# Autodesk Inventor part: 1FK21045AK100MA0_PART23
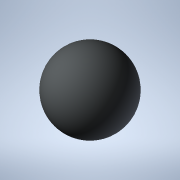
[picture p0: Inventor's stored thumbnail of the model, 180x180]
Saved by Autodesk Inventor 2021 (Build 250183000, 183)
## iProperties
Created: 2025-04
Part Number: 1FK21045AK100MA0_PART23
Material: Generic
Catalog Web Link: www.3dfindit.com
Description: -Servo synchronous motor
Document SubType Name: Modeling
Designer: psAdmin
Mass: 0.137258 g
Surface Area: 1.2868 cm^2
Volume: 0.137258 cm^3
Density: 1 g/cm^3
Appearance: PSOLRGB-212-217-219
Category: PARTsolutions
Title: 1FK21045AK100MA0_PART23
Author: Cadenas PARTsolutions
Comments: Servo synchronous motor
Sending System: PARTsolutions
Preprocessor: ST-DEVELOPER v19.3
PSOL_IDENT_0: {$CADENAS_DATA/23d-libs/siemens_ag/_cat_/e0/5f/1fk21045ak100ma0.prj},216 {VTYP=3D},{NB=1FK21045AK100
PSOL_IDENT_1: MA0_PART23},{LINA=1FK21045AK100MA0_PART23},{NN=1FK21045AK100MA0_PART23},{NOPRJ=TRUE},{DATE=19.08.202
PSOL_IDENT_2: 5 14:01:03},{GEOMDATE=30.07.2025 02:01:57},{VERSION=},{LINEID=10},{WBVAR=},{WBNUMERIC=}  {NB=1FK2104
PSOL_IDENT_3: 5AK100MA0_PART23},{LINA=1FK21045AK100MA0_PART23},{KT=DUMMY},{PREVIEW=../../../_pool_/0f/2c/p_d211_xx
PSOL_IDENT_4: _00438j.png},{DESCSHORT=SIMOTICS S-1FK2 HD, SINAMICS S210 3AC 400V-480V, 1.7 Nm, 6000 rpm},{DESCLONG=
PSOL_IDENT_5: SIMOTICS S-1FK2 HD servo motor M0=2.4 Nm; PN = 1.07 kW at nN=6000 rpm (380-480 V); PN = 0.75 kW at n
PSOL_IDENT_6: N=3000 rpm (200-240 V); with holding brake; degree of protection IP64; cylindrical shaft D19x40mm; a
PSOL_IDENT_7: bsolute encoder 22-bit + 12-bit multiturn (encoder AM22DQC); with OCC interface; plug size M17, rota
PSOL_IDENT_8: table; SIMOTICS S-1FK2 servomotorfor a wide range of uses in industrial environments. SIMOTICS S‑1FK
PSOL_IDENT_9: 2 servomotors are compact synchronous motors with a high dynamic performance that set themselves apa
PSOL_IDENT_10: rt as a result of their high power density, degree of protection and overload capability. The motors
PSOL_IDENT_11: are available in two variants: as High Dynamic variant (highest dynamic performance as a result of
PSOL_IDENT_12: the low intrinsic moment of inertia for applications demanding a high dynamic performance with low m
PSOL_IDENT_13: oved masses) - and as Compact variant (precise and stable closed-loop control for medium up to large
PSOL_IDENT_14: moved masses as a result of a medium intrinsic moment of inertia). SIMOTICSS‑1FK2 servomotors fully
PSOL_IDENT_15: exploit their strengths in a system with the SINAMICSS210 frequency converter and simple connection
PSOL_IDENT_16: using the one cable connection (OCC). Advantages include the short control and positioning times, f
PSOL_IDENT_17: ast and precise correction of disturbing quantities as well as stable control with a high dynamic pe
PSOL_IDENT_18: rformance. The servo motors can be configured to address a wide range of requirements. For example w
PSOL_IDENT_19: ith and without holding brake, IP64 or IP65 degree of protection, singleturn or multiturn absolute e
PSOL_IDENT_20: ncoders - to name just a few. Further, the servomotors are available in different shaft heights exte
PSOL_IDENT_21: nding from 20 to 100. A shaft sealing ring is available to achieve an IP65 degree of protection and
PSOL_IDENT_22: for subsequent mounting at the motor or as spare part. SIMOTICS - the optimum motor for each and eve
PSOL_IDENT_23: ry motion control application.},{INTNO=804766807114},{SUPPLIERALTNO=1FK2104-5AK10-0MA0},{MANUID=1FK2
PSOL_IDENT_24: 1045AK100MA0},{MANUNAME=Siemens},{MANUTYPEDESC=Synchronous motor 1FK2-HD 2,39 Nm},{AAU732=SIMOTICS},
PSOL_IDENT_25: {AAO057=S-1FK2},{AAU734=SIMOTICS S-1FK2 HD servo motor M0=2.4 Nm; PN = 1.07 kW at nN=6000 rpm (380-4
PSOL_IDENT_26: 80 V); PN = 0.75 kW at nN=3000 rpm (200-240 V); with holding brake; degree of protection IP64; cylin
PSOL_IDENT_27: drical shaft D19x40mm; absolute encoder 22-bit + 12-bit multiturn (encoder AM22DQC); with OCC interf
PSOL_IDENT_28: ace; plug size M17, rotatable;},{AAW338=Synchronous motor 1FK2-HD 2,39 Nm},{AAO742=SIMOTICS},{AAO663=
PSOL_IDENT_29: 4042948691236},{NOCUPEROU=1},{PRICEQUANTITY=1},{QUANTITYMIN=1},{QUANTITYINT=1},{CTN=85015100},{COO=D
PSOL_IDENT_30: E},{AAO676=1FK2104-5AK10-0MA0},{AAO677=Siemens AG},{ORDERUNIT=C62},{CONTENTUNIT=C62}
NB: 1FK21045AK100MA0_PART23
NT: Servo synchronous motor
NBSYN: $MANUID._PART23
LINA: 1FK21045AK100MA0_PART23
CATALOG: SIEMENS
PREVIEW: ../../../_pool_/0f/2c/p_d211_xx_00438j.png
DESCSHORT: SIMOTICS S-1FK2 HD, SINAMICS S210 3AC 400V-480V, 1.7 Nm, 6000 rpm
DESCLONG: SIMOTICS S-1FK2 HD servo motor M0=2.4 Nm; PN = 1.07 kW at nN=6000 rpm (380-480 V); PN = 0.75 kW at nN=3000 rpm (200-240 V); with holding brake; degree of protec
INTNO: 804766807114
SUPPLIERALTNO: 1FK2104-5AK10-0MA0
MANUID: 1FK21045AK100MA0
MANUNAME: Siemens
MANUTYPEDESC: Synchronous motor 1FK2-HD 2,39 Nm
AAU732: SIMOTICS
AAO057: S-1FK2
AAU734: SIMOTICS S-1FK2 HD servo motor M0=2.4 Nm; PN = 1.07 kW at nN=6000 rpm (380-480 V); PN = 0.75 kW at nN=3000 rpm (200-240 V); with holding brake; degree of protec
AAW338: Synchronous motor 1FK2-HD 2,39 Nm
AAO742: SIMOTICS
AAO663: 4042948691236.0
NOCUPEROU: 1
PRICEQUANTITY: 1
QUANTITYMIN: 1
QUANTITYINT: 1
CTN: 85015100
COO: DE
ARTICLENO: 1FK21045AK100MA0_PART23
BOMINFO: 1FK21045AK100MA0_PART23
CREATOR: CADENAS GmbH
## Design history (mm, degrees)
feature "2025_04_17_15_45_15_0090"
body "Solid1"
